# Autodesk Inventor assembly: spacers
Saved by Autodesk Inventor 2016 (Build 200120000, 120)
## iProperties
Created: 2018-05
Part Number: spacers
Document SubType Name: Assembly
Designer: Administrator
Title: spacers
Author: Administrator
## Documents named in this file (2)
- c:\worker\convert-fusion-mar-2018\tmp\job-1\16\output\files\8c58ff39-88bb-4352-afd9-60265520bae5\spacers_1.iam
- c:\worker\convert-fusion-mar-2018\tmp\job-1\16\output\files\8c58ff39-88bb-4352-afd9-60265520bae5\Component5_1.ipt
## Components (1 placed, 1 different names)
1. Component5:1
